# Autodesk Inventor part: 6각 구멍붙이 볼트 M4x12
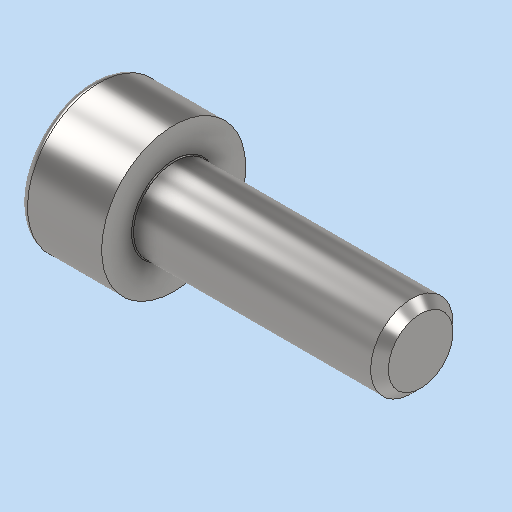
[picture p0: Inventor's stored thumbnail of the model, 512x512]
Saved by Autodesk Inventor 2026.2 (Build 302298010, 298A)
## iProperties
Created: 2026-04
Part Number: 6각 구멍붙이 볼트 M4x12
Material: 강철, 연강
Description: 6각머리 태핑 나사
Document SubType Name: Modeling
Designer: PC-2-03
Density: 7.85 g/cm^3
Appearance: 기본값
Author: jhkim
Sending System: Autodesk Inventor 2027
Preprocessor: ST-DEVELOPER v20.1
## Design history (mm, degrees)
feature "Solid1"
node "솔리드1"
